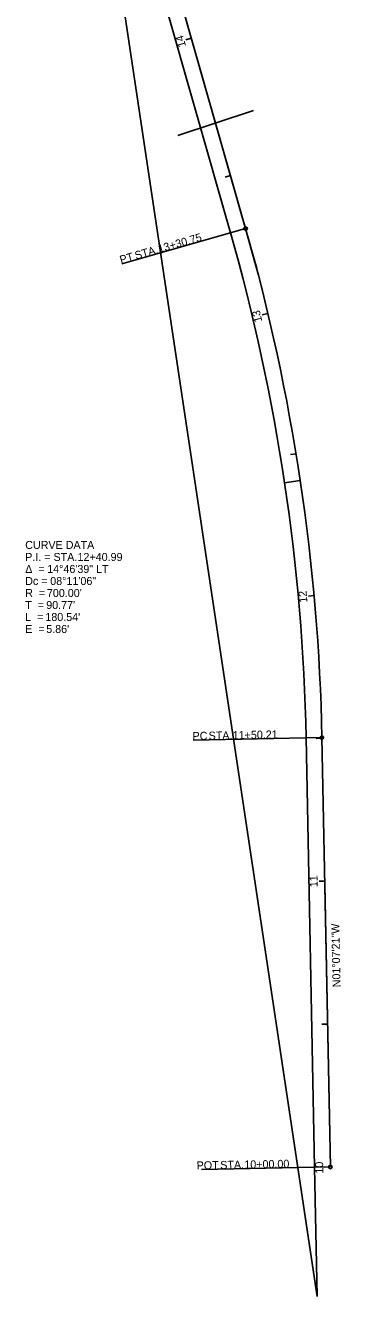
# Model space of a CAD drawing. Extents: x 215740 to 216118, y 335523 to 336438.
# Drawn here: x 216007.6 to 216117.7, y 335522.9 to 335967.6 of the extents above; entities that cross this region are included whole.
import ezdxf

# ---------------------------------------------------------------- set-up
doc = ezdxf.new("R2010")
doc.units = 0
doc.layers.add('DV_X_Property_Line', color=7, linetype='Continuous')
doc.layers.add('RW_X_Fee_RW', color=7, linetype='Continuous')

msp = doc.modelspace()

# ---------------------------------------------------------------- linework, layer by layer
at = {"layer": 'DV_X_Property_Line'}
for p, q in [((216109.52, 335522.94), (216025.7, 336082.97)), ((216079.25, 335895.01), (216026.64, 336079.71)), ((216065.57, 335963.11), (216063.65, 335962.56)), ((216060.86, 335929.05), (216087.33, 335937.8)), ((216079.27, 335915.02), (216077.34, 335914.48)), ((216084.54, 335896.51), (216041.26, 335884.19)), ((216092.31, 335866.76), (216090.37, 335866.3)), ((216102.14, 335817.75), (216100.17, 335817.42)), ((216103.61, 335808.34), (216098.17, 335807.53)), ((216108.44, 335768.16), (216106.45, 335767.97)), ((216111.19, 335718.46), (216066.2, 335717.57)), ((216108.63, 335568.16), (216105.69, 335718.35)), ((216111.19, 335718.24), (216109.19, 335718.2)), ((216112.17, 335668.25), (216110.17, 335668.21)), ((216113.15, 335618.26), (216111.15, 335618.22)), ((216114.13, 335568.27), (216069.14, 335567.39)), ((216108.63, 335568.16), (216109.52, 335522.94)), ((216114.13, 335568.27), (216112.13, 335568.23))]:
    msp.add_line(p, q, dxfattribs=at)
for centre in [(216084.54, 335896.51), (216111.19, 335718.46), (216114.13, 335568.27)]:
    msp.add_circle(centre, 0.6, dxfattribs=at)
msp.add_arc((215411.32, 335704.74), 694.5, 1.12248, 15.89995, dxfattribs=at)
at = {"layer": 'RW_X_Fee_RW'}
for p, q in [((216088.51, 335882.59), (216026.49, 336100.3)), ((216084.54, 335896.51), (216031.93, 336081.22)), ((216114.13, 335568.27), (216111.19, 335718.46)), ((216114.13, 335568.27), (216112.2, 335666.98))]:
    msp.add_line(p, q, dxfattribs=at)
msp.add_arc((215411.32, 335704.74), 700, 1.12248, 15.89995, dxfattribs=at)
msp.add_arc((215411.32, 335704.74), 700, 1.12248, 15.89995, dxfattribs=at)

# ---------------------------------------------------------------- texts
at = {"layer": 'DV_X_Property_Line'}
for s, rotation, p in [('14', 105.9, (216063.76, 335960.35)), ('13+30.75', 15.9, (216054.35, 335887.96)), (' STA. ', 15.9, (216045.26, 335885.37)), ('PT', 15.9, (216041.01, 335884.16)), ('13', 103.3827, (216090.38, 335864.09)), ('12', 95.1976, (216106.15, 335765.78)), (' STA. ', 1.1225, (216070.6, 335717.7)), ('11+50.21', 1.1225, (216080.05, 335717.89)), ('PC', 1.1225, (216066.02, 335717.61)), ('11', 91.1225, (216109.71, 335666.17)), ('N01°07\'21"W', 91.1225, (216117.7, 335631.14)), ('POT', 1.1225, (216067.46, 335567.4)), (' STA. ', 1.1225, (216074.66, 335567.54)), ('10+00.00', 1.1225, (216084.11, 335567.72)), ('10', 91.1225, (216111.67, 335565.99))]:
    msp.add_text(s, height=2.8, rotation=rotation, dxfattribs=at).set_placement(p)
for s, p in [('CURVE DATA', (216007.55, 335784.44)), ('P.I. = STA. ', (216007.55, 335780.24)), ('12+40.99', (216025.82, 335780.24)), ('Δ  = ', (216007.55, 335776.04)), ('14°46\'39" LT', (216015.23, 335776.04)), ('Dc = ', (216007.55, 335771.84)), ('08°11\'06"', (216016.29, 335771.84)), ('R  = ', (216007.55, 335767.64)), ("700.00'", (216015.13, 335767.64)), ('T  = ', (216007.55, 335763.44)), ("90.77'", (216014.89, 335763.44)), ('L  = ', (216007.55, 335759.24)), ("180.54'", (216014.59, 335759.24)), ('E  = ', (216007.55, 335755.04)), ("5.86'", (216014.89, 335755.04))]:
    msp.add_text(s, height=2.8, dxfattribs=at).set_placement(p)

doc.saveas('drawing.dxf')
